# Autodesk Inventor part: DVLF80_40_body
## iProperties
Created: 2010-03
Part Number: DVLF80_40_body
Document SubType Name: Modeling
Designer: TB
Mass: 1322.19 g
Surface Area: 1854.71 cm^2
Volume: 1322.19 cm^3
Density: 1 g/cm^3
Author: TB
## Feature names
1. Kropp [Revolution]
2. Chamfer
3. Extrusion2
4. Hole1
5. Revolution2
6. Hole2
7. Fillet1
8. Extrusion3
9. Hole3
